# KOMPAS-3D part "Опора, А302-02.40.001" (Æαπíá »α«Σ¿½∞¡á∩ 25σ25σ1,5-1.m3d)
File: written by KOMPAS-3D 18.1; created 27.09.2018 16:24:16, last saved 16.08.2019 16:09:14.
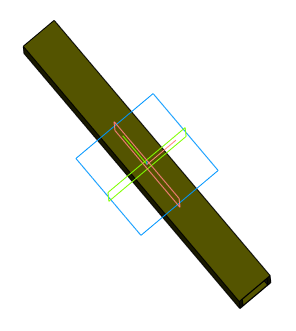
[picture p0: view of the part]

Document properties: Автор: Милов; Полное имя файла: D:\Мембранные насосы\Мембранный электропривод\А302-00.00.000 - ASTRA-302 (МЭ200)\3Д ПВХ\Отработка\Труба профильная 25х25х1,5-1.m3d

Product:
- Part/product: Опора  | designation А302-02.40.001
    Материал: Ст3кп ГОСТ 380-2005 (density 7850 kg/m3)
    Масса: 0.291894
    Раздел спецификации: Детали
    Форматы листов документа: A4
    Плотность: 7850
    source file: ..\А302-02.00.000 - ASTRA-302 (МЭ200)\А302-02.40.001 - Опора.cdw
- Part/product: Опора  | designation А302-01.40.001
    Материал: Ст3кп ГОСТ 380-2005 (density 7850 kg/m3)
    Масса: 0.186469
    Раздел спецификации: Детали
    Форматы листов документа: A4
    Плотность: 7850
    source file: ..\А302-01.40.001 - Опора.cdw

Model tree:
1. Эскиз:1
2. Операция выдавливания:1
     Расстояние 2 = 10
3. Эскиз:2  (with: Операция выдавливания:1)
4. Вырезать элемент выдавливания:1
     Расстояние 1 = 20

Expressions: (365)/5*3; L/3*2+20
